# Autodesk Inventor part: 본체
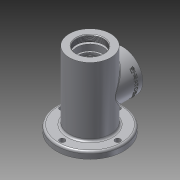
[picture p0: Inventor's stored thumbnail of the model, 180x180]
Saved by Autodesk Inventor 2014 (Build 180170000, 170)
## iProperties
Created: 2016-08
Part Number: 본체
Material: 알루미늄 6061
Document SubType Name: Modeling
Designer: 703-04
Density: 2.71 g/cm^3
Appearance: 알루미늄 - 평지
Author: 703-04
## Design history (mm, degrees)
sketch "스케치1"
  geometry: C1 r 31 at (0, 0); 1 further point
  constraints: 1 centre point, 1 coincident
  dimensions: "d0" = 62 diameter of C1
extrude "돌출1" new body sketch "스케치1" stored distance "d1" = 102; taper "d2" = 0 deg
sketch "스케치2"
  geometry: C1 r 31 at (0, 0) reference; C2 r 50 at (0, 0)
  constraints: 1 centre point, 1 coincident
  dimensions: "d3" = 100 diameter of C2
extrude "돌출2" join sketch "스케치2" distance "d4" = 10; taper "d5" = 0 deg
sketch "스케치3"
  geometry: C1 r 50 at (0, 0) reference; C2 r 31 at (0, 0)
  constraints: 1 centre point, 1 coincident
  dimensions: "d6" = 62 diameter of C2
extrude "돌출3" join sketch "스케치3" distance "d7" = 3; taper "d8" = 0 deg
sketch "스케치4"
  geometry: L1 (31, 51)-(-31, 51) reference; L2 (0, 51)-(21, 51); L3 (21, 51)-(21, 42); L4 (21, 42)-(24, 42); L5 (24, 42)-(24, 39); L6 (24, 39)-(20, 39); L7 (20, 39)-(20, 30); L8 (20, 30)-(17.5, 30); L9 (17.5, 30)-(17.5, 26.75); L10 (17.5, 26.75)-(18.5, 26.75); L11 (18.5, 26.75)-(18.5, 25); L12 (18.5, 25)-(17.5, 25); L13 (17.5, 25)-(17.5, 14); L14 (17.5, 14)-(26, 14); L15 (26, 14)-(26, -24); L16 (26, -24)-(17.5, -24); L17 (17.5, -24)-(17.5, -35); L18 (17.5, -35)-(16.5, -35); L19 (16.5, -35)-(16.5, -40); L20 (16.5, -40)-(10, -40); L21 (10, -40)-(10, -42.7); L22 (10, -42.7)-(12.5, -42.7); L23 (12.5, -42.7)-(12.5, -49.3); L24 (12.5, -49.3)-(12.904, -50); L25 (12.904, -50)-(16.404, -50); L26 (16.404, -50)-(21, -64); L27 (-31, -64)-(31, -64) reference; L28 (21, -64)-(0, -64); L29 (0, -64)-(0, 42); L30 (21, 42)-(0, 42); L31 (0, 0)-(0, 42); L32 (0, 51)-(0, 60); 1 further point
  constraints: 60 end point, 13 parallel, 10 perpendicular, 3 point on line, 2 collinear, 2 midpoint, 2 vertical, 1 coincident
  dimensions: "d9" = 60 distance of L31.start L32.end; "d10" = 21 distance of L2.start L2.end; "d11" = 9 distance of L2.end L3.end; "d12" = 3 distance of L3.end L4.end; "d13" = 3 distance of L4.end L5.end; "d14" = 4 distance of L5.end L6.end; "d15" = 9 distance of L6.end L7.end; "d16" = 2.5 distance of L7.end L8.end; "d17" = 3.25 distance of L8.end L9.end; "d18" = 1 distance of L9.end L10.end; "d19" = 1.75 distance of L10.end L11.end; "d20" = 1 distance of L11.end L12.end; "d21" = 11 distance of L12.end L13.end; "d22" = 8.5 distance of L13.end L14.end; "d23" = 38 distance of L14.end L15.end; "d24" = 8.5 distance of L15.end L16.end; "d25" = 11 distance of L16.end L17.end; "d26" = 1 distance of L17.end L18.end; "d27" = 5 distance of L18.end L19.end; "d28" = 6.5 distance of L19.end L20.end; "d29" = 2.7 distance of L20.end L21.end; "d30" = 2.5 distance of L21.end L22.end; "d31" = 6.6 distance of L22.end L23.end; "d32" = 0.7 vertical distance of L23.end L24.end; "d33" = 30 deg angle of L23 L24; "d34" = 3.5 distance of L24.end L25.end; "d37" = 21 distance from line of L26.end L29
revolve "회전1" sketch "스케치4" stored, may be unused: angle "d36" = 90 deg
sketch "스케치5"
  geometry: C1 r 31 at (0, 0) reference; 1 further point
  constraints: 1 coincident
hole "구멍1" sketch "스케치5" at (0, 0) diameter "d38" = 40.376; stored, may be unused: countersink angle "d42" = 90 deg, drill point angle "d44" = 118 deg; dims "d39" = 9, "d40" = 4, "d41" = 2, "d43" = 9
chamfer "모따기1" distance "d45" = 1; stored, may be unused: second distance "d46" = 2, angle "d47" = 45 deg
fillet "모깎기1" dims "d48" = 0.3
fillet "모깎기2" dims "d49" = 3
node "작업 평면1"
sketch "스케치6"
  geometry: L1 (31, 51)-(-31, 51) reference; C1 r 30 at (0, -5); 1 further point
  constraints: 1 centre point
  dimensions: "d51" = 60 diameter of C1; "d52" = 56 distance from line of L1 C1.centre; "d53" = 0 horizontal distance of C1.centre point (0, 0)
extrude "돌출4" join sketch "스케치6" stored distance "d54" = 3; taper "d55" = 0 deg
sketch "스케치7" dims "d57" = 48
  geometry: L1 (0, 0)-(-24, 0); C1 r 30 at (0, 0) reference; C2 r 19 at (0, 0); 1 further point
  constraints: 2 coincident, 2 end point, 1 centre point, 1 horizontal, 1 horizontal alignment, 2 other
  dimensions: "d56" = 38 diameter of C2
extrude "돌출5" cut sketch "스케치7" stored distance "d58" = 3; taper "d59" = 0 deg
hole "구멍2" sketch "스케치7" diameter "d60" = 3.242; stored, may be unused: countersink angle "d64" = 90 deg, drill point angle "d66" = 118 deg; dims "d61" = 8, "d62" = 4, "d63" = 2, "d65" = 10
sketch "스케치8" dims "d70" = 83
  geometry: L1 (0, 0)-(0, 41.5); C1 r 50 at (0, 0) reference; 1 further point
  constraints: 2 coincident, 2 end point, 1 vertical, 1 vertical alignment, 2 other
hole "구멍3" sketch "스케치8" at (0, 41.5) diameter "d71" = 8; stored, may be unused: countersink angle "d75" = 90 deg, drill point angle "d77" = 118 deg; dims "d72" = 8, "d73" = 4, "d74" = 2, "d76" = 10
node "작업 평면2"
sketch "스케치9"
  geometry: L1 (31, 51)-(-31, 51) reference; L2 (49, 25)-(49, -35) reference; 2 further points
  constraints: 1 other
  dimensions: "d82" = 10 distance from line of L2 point (39, -5); "d83" = 56 distance from line of L1 point (39, -5)
feature "엠보싱1" sketch "스케치9" dims "d84" = 0.5, "d85" = 0
chamfer "모따기2" distance "d86" = 1; stored, may be unused: second distance "d87" = 2, angle "d88" = 45 deg
fillet "모깎기3" dims "d89" = 3
node "솔리드1"
pattern_circular "원형 패턴1" dims angle "d68" = 360 deg
pattern_circular "원형 패턴2" dims angle "d79" = 360 deg
other parameters: "d35" = 42, "d50" = 49
